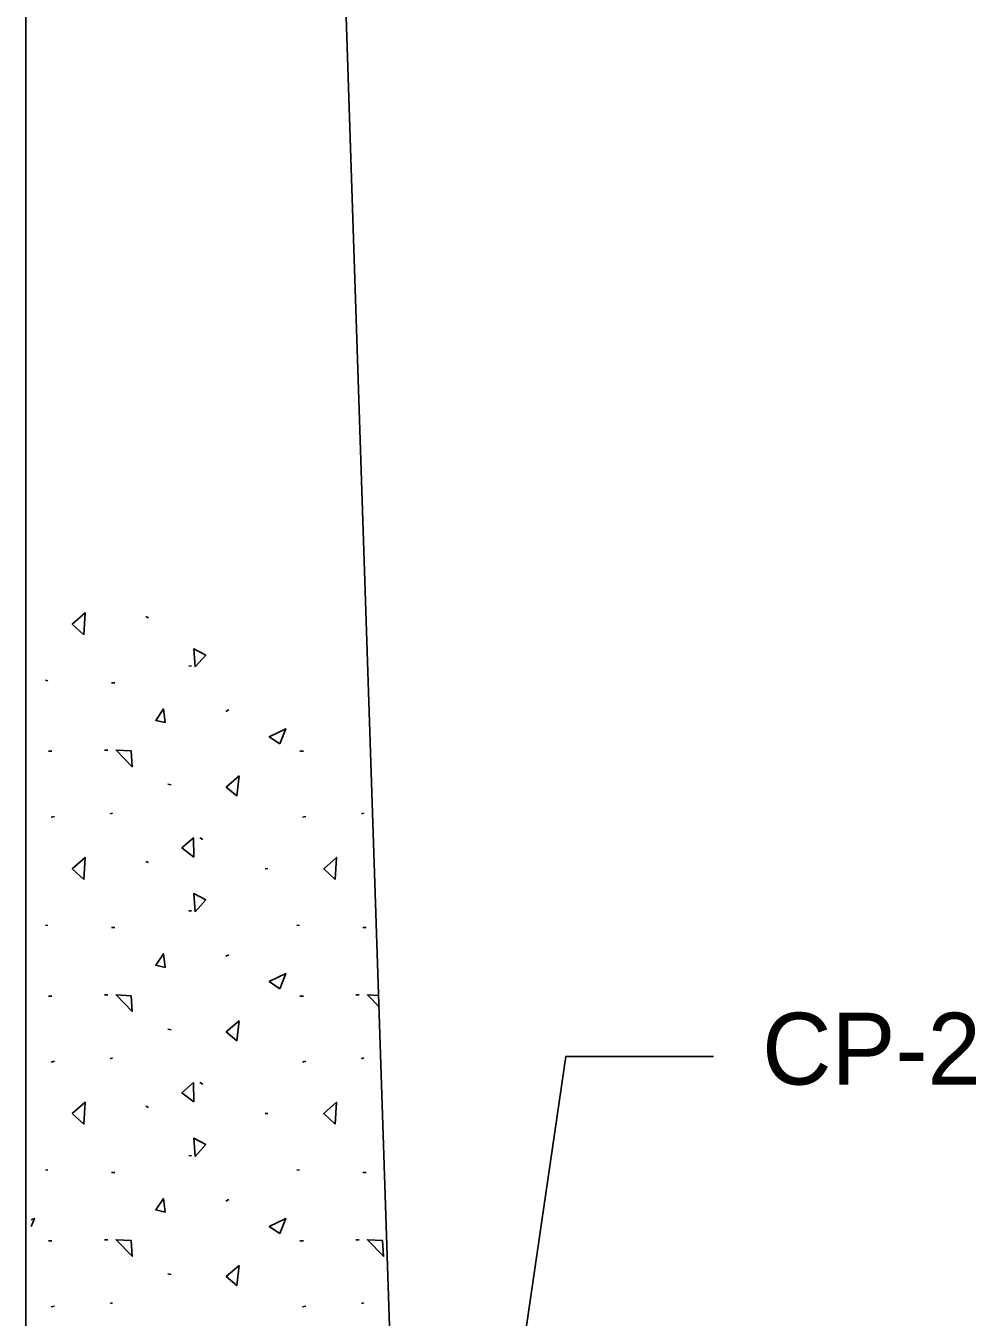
# Model space of a CAD drawing. Extents: x 44742.55 to 44745.38, y 44738.95 to 44741.13.
# Drawn here: x 44743.0946 to 44743.2139, y 44740.5111 to 44740.6733 of the extents above; entities that cross this region are included whole.
import ezdxf

# ---------------------------------------------------------------- set-up
doc = ezdxf.new("R2010")
doc.units = 0
for name, color, linetype in [('G-ANNO-PATT', 7, 'Continuous'), ('Level 10', 7, 'Continuous'), ('Level 4', 7, 'Continuous'), ('S-ANNO-DIMS', 7, 'Continuous')]:
    doc.layers.add(name, color=color, linetype=linetype)

msp = doc.modelspace()

# ---------------------------------------------------------------- linework, layer by layer
at = {"layer": 'G-ANNO-PATT'}
for p, q in [((44743.10998, 44740.59893), (44743.10964, 44740.59909)), ((44743.11538, 44740.59286), (44743.11506, 44740.59288)), ((44743.09735, 44740.59103), (44743.09704, 44740.59109)), ((44743.10576, 44740.59077), (44743.10534, 44740.59077)), ((44743.12007, 44740.58735), (44743.1197, 44740.58716)), ((44743.09785, 44740.58216), (44743.09743, 44740.58216)), ((44743.10485, 44740.58231), (44743.10445, 44740.58231)), ((44743.12942, 44740.58216), (44743.12899, 44740.58216)), ((44743.11281, 44740.57794), (44743.1124, 44740.57802)), ((44743.09819, 44740.57398), (44743.09777, 44740.57387)), ((44743.10547, 44740.57441), (44743.10517, 44740.57429)), ((44743.12975, 44740.57398), (44743.12933, 44740.57387)), ((44743.13703, 44740.57441), (44743.13673, 44740.57429)), ((44743.11678, 44740.57109), (44743.11643, 44740.5713)), ((44743.10998, 44740.56819), (44743.10964, 44740.56834)), ((44743.12497, 44740.56744), (44743.12463, 44740.56741)), ((44743.11538, 44740.56212), (44743.11506, 44740.56214)), ((44743.09735, 44740.56029), (44743.09704, 44740.56034)), ((44743.10576, 44740.56002), (44743.10534, 44740.56002)), ((44743.12892, 44740.56029), (44743.1286, 44740.56034)), ((44743.13732, 44740.56002), (44743.1369, 44740.56002)), ((44743.12007, 44740.55661), (44743.1197, 44740.55642)), ((44743.09785, 44740.55142), (44743.09743, 44740.55142)), ((44743.10485, 44740.55157), (44743.10445, 44740.55157)), ((44743.12942, 44740.55142), (44743.12899, 44740.55142)), ((44743.13642, 44740.55157), (44743.13602, 44740.55157)), ((44743.11281, 44740.5472), (44743.1124, 44740.54727)), ((44743.09819, 44740.54324), (44743.09777, 44740.54312)), ((44743.10547, 44740.54366), (44743.10517, 44740.54355)), ((44743.12975, 44740.54324), (44743.12933, 44740.54312)), ((44743.13703, 44740.54366), (44743.13673, 44740.54355)), ((44743.11678, 44740.54035), (44743.11643, 44740.54056)), ((44743.10998, 44740.53744), (44743.10964, 44740.5376)), ((44743.12497, 44740.53669), (44743.12463, 44740.53666)), ((44743.11538, 44740.53137), (44743.11506, 44740.5314)), ((44743.09735, 44740.52955), (44743.09704, 44740.5296)), ((44743.10576, 44740.52928), (44743.10534, 44740.52928)), ((44743.12892, 44740.52955), (44743.1286, 44740.5296)), ((44743.13732, 44740.52928), (44743.1369, 44740.52928)), ((44743.12007, 44740.52587), (44743.1197, 44740.52568)), ((44743.09785, 44740.52068), (44743.09743, 44740.52068)), ((44743.10485, 44740.52083), (44743.10445, 44740.52083)), ((44743.12942, 44740.52068), (44743.12899, 44740.52068)), ((44743.13642, 44740.52083), (44743.13602, 44740.52083)), ((44743.11281, 44740.51646), (44743.1124, 44740.51653)), ((44743.09819, 44740.5125), (44743.09777, 44740.51238)), ((44743.10547, 44740.51292), (44743.10517, 44740.5128)), ((44743.12975, 44740.5125), (44743.12933, 44740.51238)), ((44743.13703, 44740.51292), (44743.13673, 44740.5128))]:
    msp.add_line(p, q, dxfattribs=at)
for points in [[(44743.10185, 44740.5968), (44743.10041, 44740.59814), (44743.10201, 44740.59957)], [(44743.11583, 44740.59275), (44743.11717, 44740.59425), (44743.11567, 44740.59505)], [(44743.11207, 44740.58577), (44743.11185, 44740.58748), (44743.11089, 44740.58605)], [(44743.12646, 44740.58308), (44743.1272, 44740.58499), (44743.12513, 44740.58398)], [(44743.10778, 44740.58221), (44743.10591, 44740.58231), (44743.10794, 44740.58023)], [(44743.12134, 44740.57907), (44743.11974, 44740.57767), (44743.12106, 44740.57655)], [(44743.11567, 44740.56888), (44743.11417, 44740.57002), (44743.11561, 44740.57129)], [(44743.10185, 44740.56606), (44743.10041, 44740.5674), (44743.10201, 44740.56883)], [(44743.13342, 44740.56606), (44743.13197, 44740.5674), (44743.13357, 44740.56883)], [(44743.11583, 44740.56201), (44743.11717, 44740.56351), (44743.11567, 44740.5643)], [(44743.11207, 44740.55502), (44743.11185, 44740.55673), (44743.11089, 44740.5553)], [(44743.12646, 44740.55234), (44743.1272, 44740.55425), (44743.12513, 44740.55324)], [(44743.10778, 44740.55147), (44743.10591, 44740.55157), (44743.10794, 44740.54949)], [(44743.12134, 44740.54833), (44743.11974, 44740.54693), (44743.12106, 44740.54581)], [(44743.11567, 44740.53814), (44743.11417, 44740.53927), (44743.11561, 44740.54055)], [(44743.10185, 44740.53532), (44743.10041, 44740.53666), (44743.10201, 44740.53809)], [(44743.13342, 44740.53532), (44743.13197, 44740.53666), (44743.13357, 44740.53809)], [(44743.11583, 44740.53127), (44743.11717, 44740.53277), (44743.11567, 44740.53356)], [(44743.11207, 44740.52428), (44743.11185, 44740.52599), (44743.11089, 44740.52456)], [(44743.12646, 44740.52159), (44743.1272, 44740.52351), (44743.12513, 44740.5225)], [(44743.10778, 44740.52073), (44743.10591, 44740.52083), (44743.10794, 44740.51875)], [(44743.13935, 44740.52073), (44743.13747, 44740.52083), (44743.1395, 44740.51875)], [(44743.12134, 44740.51759), (44743.11974, 44740.51619), (44743.12106, 44740.51507)]]:
    msp.add_lwpolyline(points, close=True, dxfattribs=at)
for points in [[(44743.13892, 44740.55149), (44743.13747, 44740.55157), (44743.13897, 44740.55004)], [(44743.09525, 44740.5225), (44743.09564, 44740.52351), (44743.09526, 44740.52332)]]:
    msp.add_lwpolyline(points, dxfattribs=at)
at = {"layer": 'Level 10'}
for p, q in [((44743.09457, 44740.93372), (44743.09457, 44740.46722)), ((44743.12616, 44740.93288), (44743.14168, 44740.46722))]:
    msp.add_line(p, q, dxfattribs=at)
at = {"layer": 'S-ANNO-DIMS'}
msp.add_lwpolyline([(44743.14772, 44740.44351), (44743.16238, 44740.54384), (44743.18091, 44740.54384)], dxfattribs=at)

# ---------------------------------------------------------------- texts
at = {"layer": 'Level 4'}
msp.add_text('CP-2', height=0.00902, dxfattribs=at).set_placement((44743.18702, 44740.54031))

doc.saveas('drawing.dxf')
